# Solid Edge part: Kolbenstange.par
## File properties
Username: bmolnar
Dokumentum tartalom típus: 0
Author: bmolnar
Last saved by: bmolnar
Revision: 92
Sűrűség: 0,000 kg/m^3
Pontosság: 0,990
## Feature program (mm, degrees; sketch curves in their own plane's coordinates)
base feature "unnamed BaseFeature 1"
sketch for "unnamed Protrusion 1" plane through (24.3, 0, 0) normal (1, 0, 0) x-axis (0, -1, 0)
  circle centre (0, 0) radius 10
extrude "unnamed Protrusion 1" add finite 13.4 along +normal
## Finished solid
Body 1: solid body, 14 faces, 20 edges, 8 vertices.
  Faces by surface: plane 8, cylinder 3, cone 2, torus 1
  Edges by curve: circle 10, line 6, ellipse 2, intersection 2
Bounding box of the edges (mm; curved faces can reach further): 231.700 x 20.000 x 20.000, from (-194, -10, -10) to (37.7, 10, 10).
Cylindrical faces by radius (mm): R2.4585 x1, R5 x1, R10 x1
Conical faces (half-angle, radius in mm at the cone's reference point): 45 deg R2.8085 x1, 59 deg R1.2292 x1
Toroidal faces (ring radius, tube radius in mm): R3.8 r1.2 x1
Planar faces by outward normal: +x 1, +z 1, -x 3, -z 1, oblique 2
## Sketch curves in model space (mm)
circle centre (24.3, 0, 0) radius 10
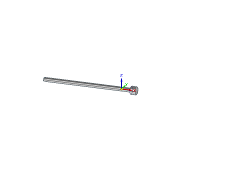
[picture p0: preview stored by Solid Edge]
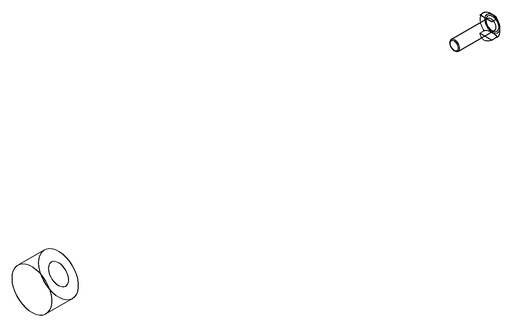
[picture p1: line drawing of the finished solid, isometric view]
